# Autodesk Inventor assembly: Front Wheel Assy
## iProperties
Length Units: 11269
Angle Units: 11279
Time Units: 11290
Mass Units: 11283
Shininess: 3
Angle Display Precision: 2
Document Length Units: 11269
Document Angle Units: 11279
Document Time Units: 11290
Document Mass Units: 11283
Document Length Units Precision: 3
Document Angle Units Precision: 2
Compacted: True
Created: 2001-08
Part Number: Front Wheel Assy
Document SubType Name: Assembly
Designer: Martin Budgell
Density: 0.0
Volumn: 0.0
Area: 0.0
PropertySet Name: Model Information
Control State: 0
Master: False
Checked Out: False
Author: Martin Budgell
